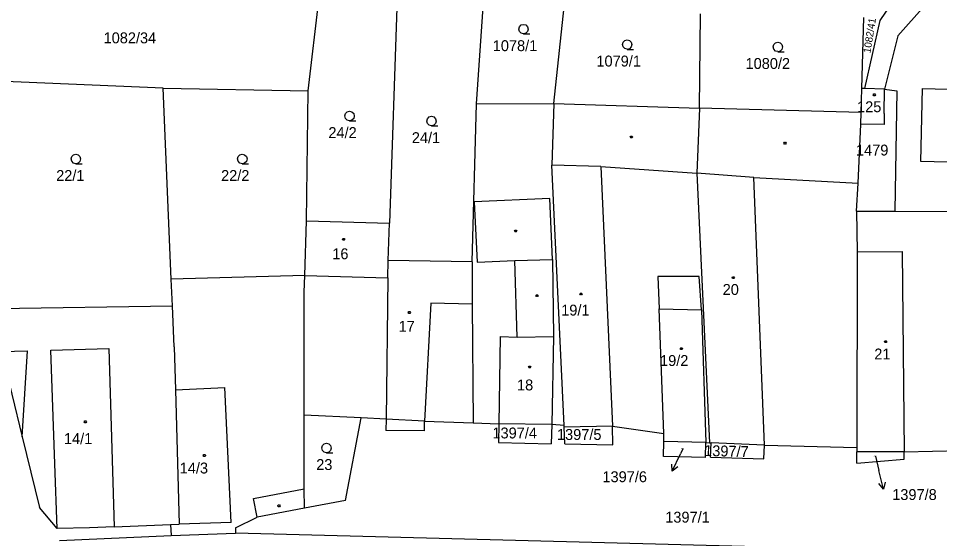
# Model space of a CAD drawing. Extents: x -852001 to -842497, y -1063614 to -1052182.
# Drawn here: x -849566 to -849422.1, y -1056338.8 to -1056257.6 of the extents above; entities that cross this region are included whole.
import ezdxf

# ---------------------------------------------------------------- set-up
doc = ezdxf.new("R2010")
doc.units = 0
for name, color, linetype in [('Default', 7, 'Continuous'), ('KN_HRANICE', 7, 'Continuous'), ('KN_KULTURY', 7, 'Continuous'), ('KN_PARCELY', 7, 'Continuous'), ('KN_SLUCKY', 7, 'Continuous')]:
    doc.layers.add(name, color=color, linetype=linetype)

# ---------------------------------------------------------------- blocks, each defined once
blk = doc.blocks.new('304')
at = {"layer": 'Default'}
blk.add_lwpolyline([(0, 0), (-0.38, 0.1), (-0.65, 0.37), (-0.75, 0.74), (-0.65, 1.11), (-0.38, 1.38), (-0.01, 1.48), (0.36, 1.38), (0.63, 1.11), (0.73, 0.73), (0.63, 0.35), (0.36, 0.08), (-0.02, -0.02), (0.98, -0.02)], dxfattribs=at)
blk = doc.blocks.new('10292')
at = {"layer": 'Default'}
blk.add_line((0, 3), (0, 0), dxfattribs=at)
blk.add_lwpolyline([(-0.5, 2), (0, 3), (0.5, 2)], dxfattribs=at)
blk = doc.blocks.new('402')
at = {"layer": 'Default'}
blk.add_lwpolyline([(0.09, 0.15), (0.18, 0), (0.09, -0.15), (-0.09, -0.15), (-0.18, 0), (-0.09, 0.15), (0.09, 0.15)], dxfattribs=at)

msp = doc.modelspace()

# ---------------------------------------------------------------- linework, layer by layer
at = {"layer": 'KN_HRANICE'}
for p, q in [((-849520.73, -1056268.91), (-849518.79, -1056252.77)), ((-849506.8, -1056253.15), (-849508.04, -1056289.59)), ((-849494.45, -1056270.95), (-849493.22, -1056253.57)), ((-849482.35, -1056270.93), (-849480.53, -1056253.97)), ((-849431.37, -1056257.95), (-849429.59, -1056255.35)), ((-849424.4, -1056255.6), (-849428.61, -1056260.33)), ((-849459.61, -1056271.66), (-849459.46, -1056256.93)), ((-849434.27, -1056268.55), (-849433.96, -1056257.48)), ((-849433.77, -1056268.56), (-849431.37, -1056257.95)), ((-849428.61, -1056260.33), (-849430.72, -1056268.66)), ((-849543.36, -1056268.51), (-849571.14, -1056267.35)), ((-849543.36, -1056268.51), (-849520.73, -1056268.91)), ((-849542.09, -1056298.32), (-849543.36, -1056268.51)), ((-849521, -1056289.21), (-849520.73, -1056268.91)), ((-849434.34, -1056272.32), (-849434.27, -1056268.55)), ((-849433.77, -1056268.56), (-849434.27, -1056268.55)), ((-849430.72, -1056268.66), (-849433.77, -1056268.56)), ((-849430.76, -1056272.49), (-849430.72, -1056268.66)), ((-849430.72, -1056268.66), (-849428.8, -1056268.93)), ((-849428.8, -1056268.93), (-849429.11, -1056287.73)), ((-849425.04, -1056279.98), (-849424.78, -1056268.57)), ((-849424.78, -1056268.57), (-849403.43, -1056269.1)), ((-849495.12, -1056295.64), (-849494.45, -1056270.95)), ((-849494.45, -1056270.95), (-849482.35, -1056270.93)), ((-849482.35, -1056270.93), (-849482.67, -1056280.51)), ((-849482.35, -1056270.93), (-849459.61, -1056271.66)), ((-849459.61, -1056271.66), (-849460.03, -1056281.78)), ((-849434.34, -1056272.32), (-849459.61, -1056271.66)), ((-849434.38, -1056274.15), (-849434.34, -1056272.32)), ((-849430.76, -1056272.49), (-849430.78, -1056274.18)), ((-849434.84, -1056283.32), (-849434.38, -1056274.15)), ((-849430.78, -1056274.18), (-849434.38, -1056274.15)), ((-849480.75, -1056321.14), (-849482.67, -1056280.51)), ((-849415.41, -1056280.22), (-849425.04, -1056279.98)), ((-849460.03, -1056281.78), (-849458.02, -1056323.85)), ((-849435.06, -1056287.7), (-849434.84, -1056283.32)), ((-849435.06, -1056287.7), (-849434.99, -1056294.05)), ((-849435.06, -1056287.7), (-849429.11, -1056287.73)), ((-849429.11, -1056287.73), (-849411.38, -1056287.83)), ((-849521.24, -1056297.73), (-849521, -1056289.21)), ((-849521, -1056289.21), (-849508.04, -1056289.59)), ((-849508.22, -1056295.39), (-849508.04, -1056289.59)), ((-849434.99, -1056294.05), (-849435.03, -1056324.6)), ((-849508.3, -1056298.1), (-849508.22, -1056295.39)), ((-849495.12, -1056295.64), (-849508.22, -1056295.39)), ((-849495.12, -1056295.64), (-849495.08, -1056302.24)), ((-849521.24, -1056297.73), (-849542.09, -1056298.32)), ((-849521.32, -1056300.37), (-849521.24, -1056297.73)), ((-849508.3, -1056298.1), (-849508.54, -1056320.18)), ((-849459.67, -1056297.88), (-849466.12, -1056297.93)), ((-849466.12, -1056297.93), (-849465.89, -1056302.94)), ((-849459.31, -1056303.12), (-849459.67, -1056297.88)), ((-849541.91, -1056302.5), (-849542.09, -1056298.32)), ((-849521.32, -1056319.52), (-849521.32, -1056300.37)), ((-849495.08, -1056302.24), (-849494.97, -1056320.74)), ((-849569.5, -1056302.91), (-849541.91, -1056302.5)), ((-849541.64, -1056308.88), (-849541.91, -1056302.5)), ((-849465.19, -1056322.38), (-849465.89, -1056302.94)), ((-849459.31, -1056303.12), (-849458.61, -1056323.81)), ((-849568.61, -1056309.6), (-849564.57, -1056309.49)), ((-849568.61, -1056309.6), (-849565.38, -1056322.92)), ((-849565.38, -1056322.92), (-849564.57, -1056309.49)), ((-849541.64, -1056308.88), (-849541.45, -1056315.57)), ((-849541.45, -1056315.57), (-849540.85, -1056336.53)), ((-849521.32, -1056331.05), (-849521.32, -1056319.52)), ((-849512.43, -1056319.98), (-849521.32, -1056319.52)), ((-849514.89, -1056332.85), (-849512.43, -1056319.98)), ((-849508.54, -1056320.18), (-849512.43, -1056319.98)), ((-849508.54, -1056320.18), (-849508.59, -1056321.95)), ((-849502.57, -1056321.97), (-849502.53, -1056320.49)), ((-849502.53, -1056320.49), (-849494.97, -1056320.74)), ((-849494.97, -1056320.74), (-849490.92, -1056320.87)), ((-849490.92, -1056320.87), (-849490.97, -1056323.82)), ((-849482.68, -1056320.99), (-849490.92, -1056320.87)), ((-849482.68, -1056320.99), (-849482.75, -1056323.99)), ((-849480.75, -1056321.14), (-849482.68, -1056320.99)), ((-849480.74, -1056321.39), (-849480.75, -1056321.14)), ((-849502.57, -1056321.97), (-849508.59, -1056321.95)), ((-849473.17, -1056321.25), (-849480.74, -1056321.39)), ((-849480.64, -1056323.99), (-849480.74, -1056321.39)), ((-849473.12, -1056324.15), (-849473.17, -1056321.25)), ((-849473.17, -1056321.25), (-849465.19, -1056322.38)), ((-849465.18, -1056323.63), (-849465.19, -1056322.38)), ((-849565.38, -1056322.92), (-849562.7, -1056333.97)), ((-849490.97, -1056323.82), (-849482.75, -1056323.99)), ((-849480.64, -1056323.99), (-849473.12, -1056324.15)), ((-849465.24, -1056325.98), (-849465.18, -1056323.63)), ((-849458.61, -1056323.81), (-849465.18, -1056323.63)), ((-849458.67, -1056326.16), (-849458.61, -1056323.81)), ((-849458.61, -1056323.81), (-849458.02, -1056323.85)), ((-849458.02, -1056323.85), (-849457.77, -1056323.86)), ((-849457.87, -1056326.11), (-849457.77, -1056323.86)), ((-849449.46, -1056324.22), (-849457.77, -1056323.86)), ((-849449.55, -1056326.37), (-849449.46, -1056324.22)), ((-849449.46, -1056324.22), (-849435.03, -1056324.6)), ((-849435.03, -1056324.6), (-849435.03, -1056325.25)), ((-849427.65, -1056325.24), (-849435.03, -1056325.25)), ((-849435.03, -1056327.05), (-849435.03, -1056325.25)), ((-849427.65, -1056325.24), (-849414.63, -1056324.97)), ((-849427.65, -1056326.39), (-849427.65, -1056325.24)), ((-849458.67, -1056326.16), (-849465.24, -1056325.98)), ((-849457.87, -1056326.11), (-849449.55, -1056326.37)), ((-849435.03, -1056327.05), (-849427.65, -1056326.39)), ((-849521.3, -1056334.07), (-849521.32, -1056331.05)), ((-849559.9, -1056337.24), (-849562.7, -1056333.97)), ((-849521.3, -1056334.07), (-849528.68, -1056335.48)), ((-849514.89, -1056332.85), (-849521.3, -1056334.07)), ((-849532.07, -1056337.11), (-849528.68, -1056335.48)), ((-849551.04, -1056336.99), (-849554.88, -1056337.1)), ((-849551.04, -1056336.99), (-849542.24, -1056336.61)), ((-849542.24, -1056336.61), (-849540.85, -1056336.53)), ((-849542.24, -1056336.61), (-849542.14, -1056338.3)), ((-849554.88, -1056337.1), (-849559.9, -1056337.24)), ((-849559.57, -1056339.1), (-849542.14, -1056338.3)), ((-849542.14, -1056338.3), (-849532.06, -1056337.93)), ((-849532.07, -1056337.11), (-849532.06, -1056337.93)), ((-849406.11, -1056341.28), (-849532.06, -1056337.93))]:
    msp.add_line(p, q, dxfattribs=at)
at = {"layer": 'KN_PARCELY'}
for p, q in [((-849462.18, -1056324.8), (-849462.57, -1056325.6)), ((-849432.09, -1056325.94), (-849431.57, -1056328.16))]:
    msp.add_line(p, q, dxfattribs=at)
at = {"layer": 'KN_SLUCKY'}
for p, q in [((-849475.02, -1056280.76), (-849482.67, -1056280.51)), ((-849475.02, -1056280.76), (-849460.03, -1056281.78)), ((-849475.02, -1056280.76), (-849473.17, -1056321.25)), ((-849451.09, -1056282.46), (-849460.03, -1056281.78)), ((-849449.46, -1056324.22), (-849451.09, -1056282.46)), ((-849451.09, -1056282.46), (-849434.84, -1056283.32)), ((-849482.97, -1056285.71), (-849494.77, -1056286.24)), ((-849494.77, -1056286.24), (-849494.34, -1056295.65)), ((-849482.56, -1056295.24), (-849482.97, -1056285.71)), ((-849488.42, -1056295.39), (-849482.56, -1056295.24)), ((-849482.56, -1056295.24), (-849482.38, -1056307.29)), ((-849434.99, -1056294.05), (-849427.93, -1056293.99)), ((-849427.93, -1056293.99), (-849427.65, -1056325.24)), ((-849494.34, -1056295.65), (-849488.42, -1056295.39)), ((-849488.1, -1056307.35), (-849488.42, -1056295.39)), ((-849521.24, -1056297.73), (-849508.3, -1056298.1)), ((-849501.58, -1056302.08), (-849502.53, -1056320.49)), ((-849495.08, -1056302.24), (-849501.58, -1056302.08)), ((-849465.89, -1056302.94), (-849459.31, -1056303.12)), ((-849490.71, -1056307.29), (-849490.92, -1056320.87)), ((-849490.71, -1056307.29), (-849488.1, -1056307.35)), ((-849488.1, -1056307.35), (-849482.38, -1056307.29)), ((-849482.38, -1056307.29), (-849482.68, -1056320.99)), ((-849560.9, -1056309.39), (-849551.84, -1056309.15)), ((-849560.26, -1056327.16), (-849560.9, -1056309.39)), ((-849551.84, -1056309.15), (-849551.04, -1056336.99)), ((-849541.45, -1056315.57), (-849533.76, -1056315.2)), ((-849532.75, -1056336.3), (-849533.76, -1056315.2)), ((-849502.53, -1056320.49), (-849508.54, -1056320.18)), ((-849559.9, -1056337.24), (-849560.26, -1056327.16)), ((-849529.28, -1056332.55), (-849521.32, -1056331.05)), ((-849528.68, -1056335.48), (-849529.28, -1056332.55)), ((-849532.75, -1056336.3), (-849540.85, -1056336.53))]:
    msp.add_line(p, q, dxfattribs=at)

# ---------------------------------------------------------------- block references
at = {"layer": 'KN_KULTURY'}
for name, p in [('304', (-849487.07, -1056260.04)), ('304', (-849470.88, -1056262.44)), ('304', (-849447.35, -1056262.82)), ('402', (-849432.3, -1056269.56)), ('304', (-849514.24, -1056273.6)), ('304', (-849501.45, -1056274.39)), ('402', (-849470.23, -1056276.14)), ('402', (-849446.26, -1056277.09)), ('304', (-849557, -1056280.3)), ('304', (-849531, -1056280.3)), ('402', (-849488.3, -1056290.81)), ('402', (-849515.19, -1056292.11)), ('402', (-849454.34, -1056298.09)), ('402', (-849484.97, -1056300.89)), ('402', (-849478.12, -1056300.63)), ('402', (-849504.91, -1056303.51)), ('402', (-849430.54, -1056308.07)), ('402', (-849462.42, -1056309.16)), ('402', (-849486.13, -1056312.03)), ('402', (-849555.53, -1056320.57)), ('304', (-849517.84, -1056325.4)), ('402', (-849536.92, -1056325.84)), ('402', (-849525.29, -1056333.7))]:
    msp.add_blockref(name, p, dxfattribs=at)
at = {"layer": 'KN_PARCELY'}
for p, rotation in [((-849462.57, -1056325.6), 153.95376000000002), ((-849431.57, -1056328.16), -166.85592700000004)]:
    msp.add_blockref('10292', p, dxfattribs=dict(at, rotation=rotation))

# ---------------------------------------------------------------- texts
for s, height, rotation, p in [('1082/41', 1.14, 80.73, (-849432.91, -1056263.11)), ('1397/7', 1.7, 358.614, (-849458.89, -1056325.91))]:
    msp.add_text(s, height=height, rotation=rotation, dxfattribs=at).set_placement(p)
for s, height, p in [('1082/34', 1.7, (-849552.67, -1056261.52)), ('1078/1', 1.7, (-849491.89, -1056262.74)), ('1079/1', 1.7, (-849475.7, -1056265.14)), ('1080/2', 1.7, (-849452.41, -1056265.52)), ('125', 1.7, (-849434.99, -1056272.27)), ('24/2', 1.7, (-849517.56, -1056276.3)), ('24/1', 1.7, (-849504.53, -1056277.09)), ('1479', 1.7, (-849435.16, -1056279.03)), ('22/1', 1.7, (-849560.08, -1056283)), ('22/2', 1.7, (-849534.32, -1056283)), ('16', 1.7, (-849516.95, -1056295.21)), ('20', 1.7, (-849455.98, -1056300.78)), ('19/1', 1.7, (-849481.2, -1056304)), ('17', 1.7, (-849506.6, -1056306.53)), ('21', 1.7, (-849432.3, -1056310.85)), ('19/2', 1.7, (-849465.76, -1056311.87)), ('18', 1.7, (-849488.1, -1056315.68)), ('14/1', 1.7, (-849558.86, -1056324.05)), ('1397/4', 1.7, (-849491.94, -1056323.17)), ('1397/5', 1.7, (-849481.86, -1056323.41)), ('1397/6', 0.1, (-849462.48, -1056324.8)), ('14/3', 1.7, (-849540.78, -1056328.64)), ('23', 1.7, (-849519.46, -1056328.1)), ('1397/8', 0.1, (-849432.39, -1056325.94)), ('1397/6', 1.7, (-849474.76, -1056330)), ('1397/8', 1.7, (-849429.5, -1056332.78)), ('1397/1', 1.7, (-849464.95, -1056336.31))]:
    msp.add_text(s, height=height, dxfattribs=at).set_placement(p)

doc.saveas('drawing.dxf')
